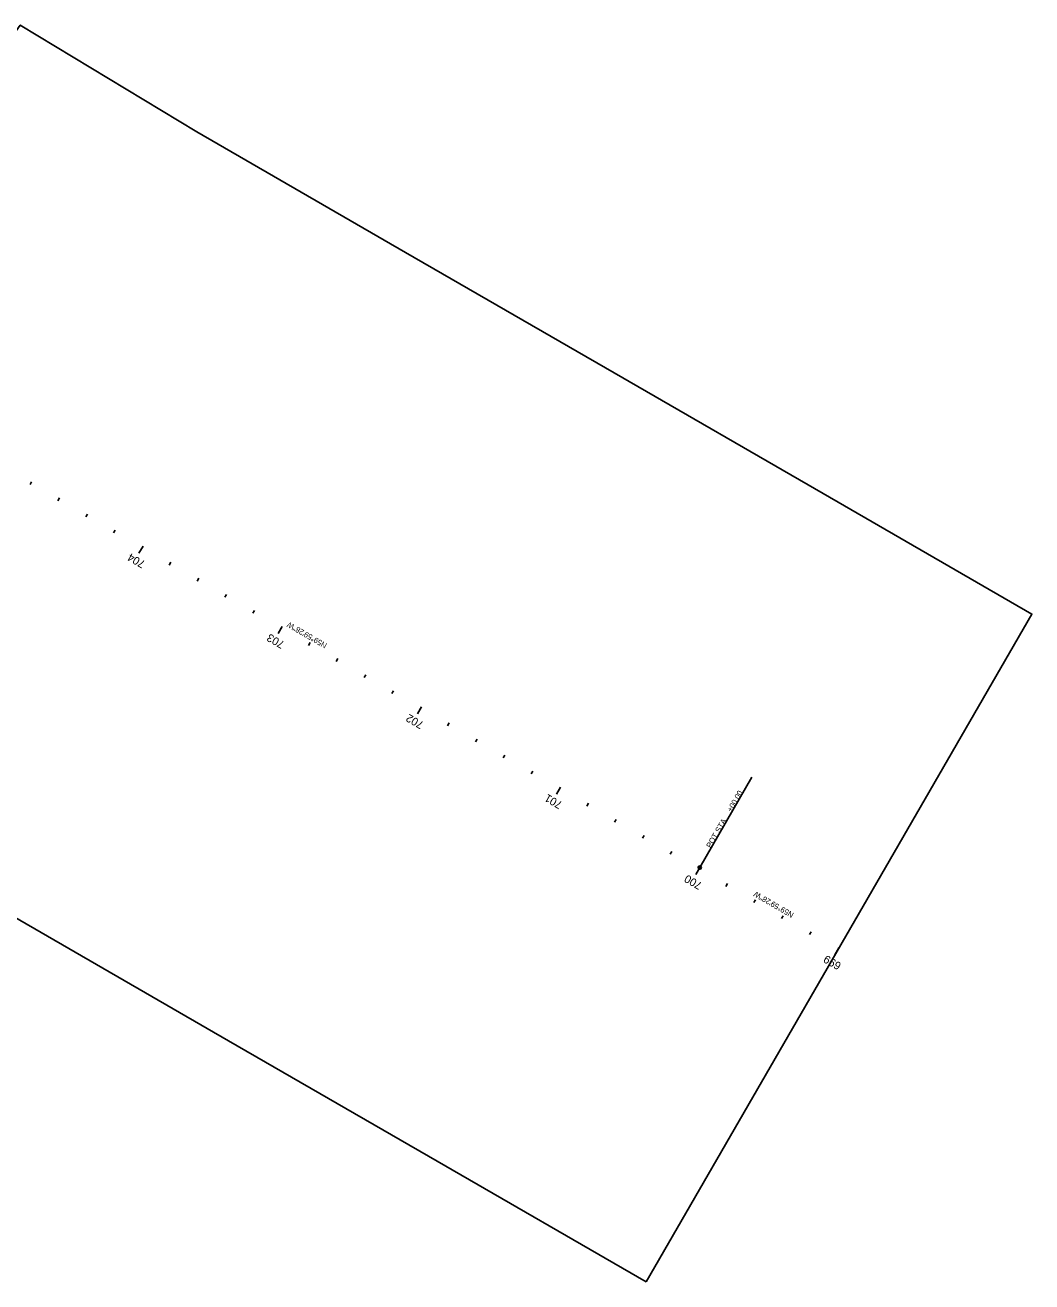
# Model space of a CAD drawing. Extents: x 2005381 to 2007040, y 402385 to 405116.
# Drawn here: x 2006414 to 2007040, y 402385 to 403167 of the extents above; entities that cross this region are included whole.
import ezdxf

# ---------------------------------------------------------------- set-up
doc = ezdxf.new("R2010")
doc.units = 0
for name, color, linetype in [('ClipDrawingBound_dp', 7, 'Continuous'), ('TextAlgnCardinalPnt', 7, 'Continuous'), ('TextAlgnStation100', 7, 'Continuous'), ('TextAlgnStation1000', 7, 'Continuous'), ('TextAlgnStation500', 7, 'Continuous'), ('TextAlgnStation5000', 7, 'Continuous'), ('TextAlgnTangent', 7, 'Continuous'), ('TextAlgnTicks100', 7, 'Continuous'), ('TextAlgnTicks1000', 7, 'Continuous'), ('TextAlgnTicks500', 7, 'Continuous'), ('TextAlgnTicks5000', 7, 'Continuous')]:
    doc.layers.add(name, color=color, linetype=linetype)

msp = doc.modelspace()

# ---------------------------------------------------------------- linework, layer by layer
at = {"layer": 'ClipDrawingBound_dp'}
msp.add_lwpolyline([(2006800.2, 402385.11), (2007040.26, 402800.77), (2006910.37, 402875.79), (2006780.48, 402950.81), (2006650.59, 403025.83), (2006520.69, 403100.85), (2006410.87, 403167.27), (2006134.42, 402774.87), (2006280.63, 402685.19), (2006410.52, 402610.17), (2006540.41, 402535.15), (2006670.31, 402460.13)], close=True, dxfattribs=at)
at = {"layer": 'TextAlgnCardinalPnt'}
msp.add_line((2006833.64, 402642.95), (2006866.14, 402699.24), dxfattribs=at)
msp.add_circle((2006833.64, 402642.95), 1, dxfattribs=at)
at = {"layer": 'TextAlgnTicks100'}
for p, q in [((2006417.98, 402883.02), (2006416.98, 402881.29)), ((2006435.3, 402873.01), (2006434.3, 402871.28)), ((2006452.62, 402863.01), (2006451.62, 402861.28)), ((2006469.94, 402853.01), (2006468.94, 402851.28)), ((2006487.26, 402843.01), (2006484.76, 402838.68)), ((2006504.58, 402833), (2006503.58, 402831.27)), ((2006521.89, 402823), (2006520.89, 402821.27)), ((2006539.21, 402813), (2006538.21, 402811.27)), ((2006556.53, 402803), (2006555.53, 402801.26)), ((2006573.85, 402792.99), (2006571.35, 402788.66)), ((2006591.17, 402782.99), (2006590.17, 402781.26)), ((2006608.49, 402772.99), (2006607.49, 402771.26)), ((2006625.81, 402762.99), (2006624.81, 402761.25)), ((2006643.13, 402752.98), (2006642.13, 402751.25)), ((2006660.45, 402742.98), (2006657.95, 402738.65)), ((2006677.76, 402732.98), (2006676.76, 402731.25)), ((2006695.08, 402722.97), (2006694.08, 402721.24)), ((2006712.4, 402712.97), (2006711.4, 402711.24)), ((2006729.72, 402702.97), (2006728.72, 402701.24)), ((2006747.04, 402692.97), (2006744.54, 402688.64)), ((2006764.36, 402682.96), (2006763.36, 402681.23)), ((2006781.68, 402672.96), (2006780.68, 402671.23)), ((2006799, 402662.96), (2006798, 402661.23)), ((2006816.32, 402652.96), (2006815.32, 402651.22)), ((2006833.64, 402642.95), (2006831.13, 402638.62)), ((2006850.95, 402632.95), (2006849.95, 402631.22)), ((2006868.27, 402622.95), (2006867.27, 402621.22)), ((2006885.59, 402612.95), (2006884.59, 402611.21)), ((2006902.91, 402602.94), (2006901.91, 402601.21)), ((2006920.23, 402592.94), (2006917.73, 402588.61))]:
    msp.add_line(p, q, dxfattribs=at)
at = {"layer": 'TextAlgnTicks1000'}
for p, q in [((2006487.26, 402843.01), (2006486.26, 402841.28)), ((2006660.45, 402742.98), (2006659.45, 402741.25)), ((2006833.64, 402642.95), (2006831.13, 402638.62))]:
    msp.add_line(p, q, dxfattribs=at)
at = {"layer": 'TextAlgnTicks500'}
for p, q in [((2006487.26, 402843.01), (2006486.26, 402841.28)), ((2006573.85, 402792.99), (2006572.85, 402791.26)), ((2006660.45, 402742.98), (2006659.45, 402741.25)), ((2006747.04, 402692.97), (2006746.04, 402691.23)), ((2006833.64, 402642.95), (2006831.13, 402638.62)), ((2006920.23, 402592.94), (2006919.23, 402591.21))]:
    msp.add_line(p, q, dxfattribs=at)
at = {"layer": 'TextAlgnTicks5000'}
msp.add_line((2006833.64, 402642.95), (2006831.13, 402638.62), dxfattribs=at)

# ---------------------------------------------------------------- texts
at = {"layer": 'TextAlgnCardinalPnt'}
for s, p in [('+00.00', (2006853.41, 402677.19)), (' STA. ', (2006845.34, 402663.23)), ('POT', (2006840.47, 402654.78))]:
    msp.add_text(s, height=3.48, rotation=59.99111, dxfattribs=at).set_placement(p)
at = {"layer": 'TextAlgnStation100'}
for s, p in [('704', (2006489.1, 402833.28)), ('703', (2006575.78, 402783.22)), ('702', (2006662.37, 402733.2)), ('701', (2006748.58, 402683.42)), ('700', (2006835.51, 402633.21)), ('699', (2006922.11, 402583.19))]:
    msp.add_text(s, height=4.98, rotation=149.99111, dxfattribs=at).set_placement(p)
at = {"layer": 'TextAlgnStation1000'}
msp.add_text('700', height=4.98, rotation=149.99111, dxfattribs=at).set_placement((2006835.51, 402633.21))
at = {"layer": 'TextAlgnStation500'}
msp.add_text('700', height=4.98, rotation=149.99111, dxfattribs=at).set_placement((2006835.51, 402633.21))
at = {"layer": 'TextAlgnStation5000'}
msp.add_text('700', height=4.98, rotation=149.99111, dxfattribs=at).set_placement((2006835.51, 402633.21))
at = {"layer": 'TextAlgnTangent'}
for p in [(2006602.09, 402782.22), (2006892.49, 402614.49)]:
    msp.add_text('N59°59\'28"W', height=3.48, rotation=149.99111, dxfattribs=at).set_placement(p)

doc.saveas('drawing.dxf')
